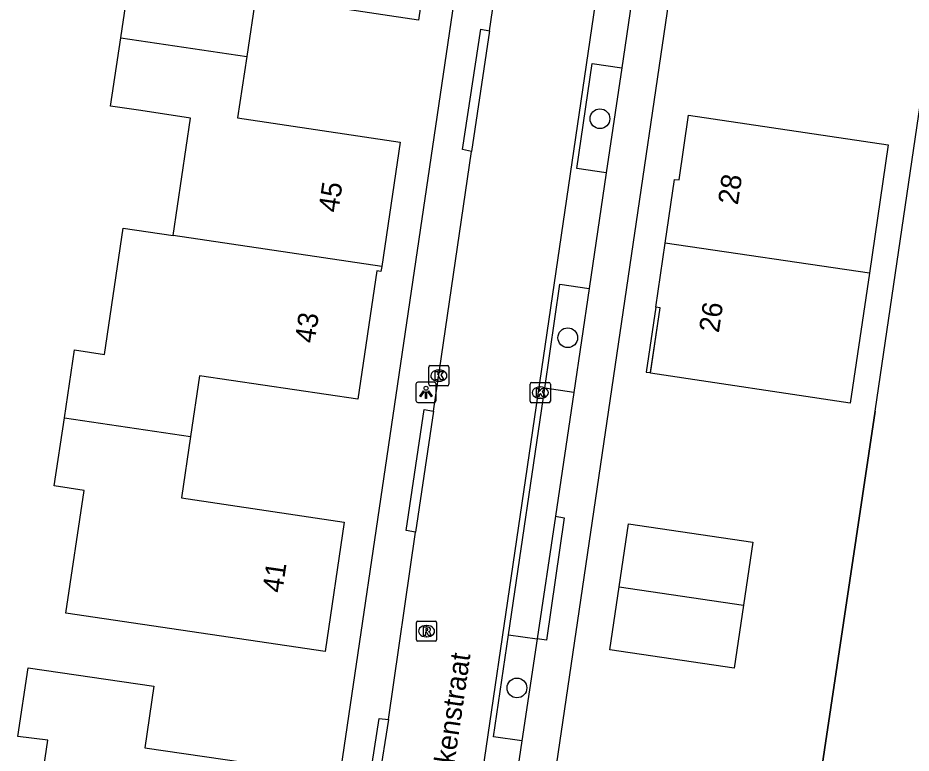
# Model space of a CAD drawing. Extents: x 164150 to 165261, y 382513 to 383432.
# Drawn here: x 164443.48 to 164487.69, y 383126.15 to 383162.53 of the extents above; entities that cross this region are included whole.
import ezdxf

# ---------------------------------------------------------------- set-up
doc = ezdxf.new("R2010")
doc.units = 0
for name, color, linetype in [('IMGEO_Boom', 7, 'Continuous'), ('IMGEO_Groenvoorziening', 7, 'Continuous'), ('IMGEO_Hek', 7, 'Continuous'), ('IMGEO_Kolk', 7, 'Continuous'), ('IMGEO_Lichtpunt', 7, 'Continuous'), ('IMGEO_Openbare_ruimte_label', 7, 'Continuous'), ('IMGEO_Pand', 7, 'Continuous'), ('IMGEO_Pand_nummerreeks', 7, 'Continuous'), ('IMGEO_Pand_overbouw', 7, 'Continuous'), ('IMGEO_Parkeervlak_open', 7, 'Continuous'), ('IMGEO_Rijbaan_lokaal_open', 7, 'Continuous'), ('IMGEO_Rioolput', 7, 'Continuous'), ('IMGEO_Voetpad_open', 7, 'Continuous')]:
    doc.layers.add(name, color=color, linetype=linetype)

msp = doc.modelspace()

# ---------------------------------------------------------------- linework, layer by layer
at = {"layer": 'IMGEO_Boom'}
for centre in [(164472.292, 383157.539), (164470.699, 383146.704), (164468.185, 383129.378)]:
    msp.add_circle(centre, 0.489, dxfattribs=at)
at = {"layer": 'IMGEO_Groenvoorziening'}
msp.add_lwpolyline([(164471.706, 383047.448), (164472.669, 383053.926), (164475.824, 383075.164), (164477.779, 383088.109), (164480.994, 383109.14), (164482.781, 383122.124), (164485.913, 383143.071), (164487.83, 383156.078), (164491.989, 383184.295), (164492.391, 383187.03)], dxfattribs=at)
at = {"layer": 'IMGEO_Hek'}
msp.add_lwpolyline([(164485.913, 383143.071), (164482.781, 383122.124)], dxfattribs=at)
at = {"layer": 'IMGEO_Kolk'}
for p, q in [((164463.817, 383144.4), (164463.817, 383145.252)), ((164463.892, 383145.326), (164464.744, 383145.326)), ((164464.818, 383145.252), (164464.818, 383144.4)), ((164464.305, 383145.106), (164464.33, 383145.106)), ((164464.328, 383144.546), (164464.303, 383144.546)), ((164468.836, 383143.562), (164468.836, 383144.414)), ((164468.911, 383144.488), (164469.763, 383144.488)), ((164469.837, 383144.414), (164469.837, 383143.562)), ((164464.744, 383144.326), (164463.892, 383144.326)), ((164469.324, 383144.268), (164469.349, 383144.268)), ((164469.763, 383143.488), (164468.911, 383143.488)), ((164469.347, 383143.708), (164469.322, 383143.708))]:
    msp.add_line(p, q, dxfattribs=at)
for points in [[(164463.817, 383144.4), (164463.817, 383145.252)], [(164463.892, 383145.326), (164464.744, 383145.326)], [(164464.818, 383145.252), (164464.818, 383144.4)], [(164464.138, 383145.026), (164464.261, 383145.026), (164464.261, 383144.875), (164464.391, 383145.026), (164464.555, 383145.026), (164464.409, 383144.875), (164464.562, 383144.626), (164464.41, 383144.626), (164464.325, 383144.79), (164464.261, 383144.723), (164464.261, 383144.626), (164464.138, 383144.626), (164464.138, 383145.026)], [(164468.836, 383143.562), (164468.836, 383144.414)], [(164468.911, 383144.488), (164469.763, 383144.488)], [(164469.837, 383144.414), (164469.837, 383143.562)], [(164464.744, 383144.326), (164463.892, 383144.326)], [(164469.157, 383144.188), (164469.28, 383144.188), (164469.28, 383144.037), (164469.41, 383144.188), (164469.574, 383144.188), (164469.428, 383144.037), (164469.581, 383143.788), (164469.429, 383143.788), (164469.344, 383143.952), (164469.28, 383143.885), (164469.28, 383143.788), (164469.157, 383143.788), (164469.157, 383144.188)], [(164469.763, 383143.488), (164468.911, 383143.488)]]:
    msp.add_lwpolyline(points, dxfattribs=at)
for centre, start, end in [((164463.894, 383145.25), 91.552, 178.448), ((164463.894, 383145.25), 91.552, 178.448), ((164464.742, 383145.25), 1.552, 88.448), ((164464.742, 383145.25), 1.552, 88.448), ((164463.894, 383144.402), 181.552, 268.448), ((164463.894, 383144.402), 181.552, 268.448), ((164464.742, 383144.402), 271.552, 358.448), ((164464.742, 383144.402), 271.552, 358.448), ((164468.913, 383144.412), 91.552, 178.448), ((164468.913, 383144.412), 91.552, 178.448), ((164469.761, 383144.412), 1.552, 88.448), ((164469.761, 383144.412), 1.552, 88.448), ((164468.913, 383143.564), 181.552, 268.448), ((164468.913, 383143.564), 181.552, 268.448), ((164469.761, 383143.564), 271.552, 358.448), ((164469.761, 383143.564), 271.552, 358.448)]:
    msp.add_arc(centre, 0.0765, start, end, dxfattribs=at)
for centre, major_axis, ratio, start_param, end_param in [((164464.304, 383144.826), (-0.387, 0.002), 0.722429, 4.712389, 7.853982), ((164464.329, 383144.826), (-0.39, 0.002), 0.717154, 1.570796, 4.712389), ((164469.323, 383143.988), (-0.387, 0.002), 0.722429, 4.712389, 7.853982), ((164469.348, 383143.988), (-0.39, 0.002), 0.717154, 1.570796, 4.712389)]:
    msp.add_ellipse(centre, major_axis=major_axis, ratio=ratio, start_param=start_param, end_param=end_param, dxfattribs=at)
at = {"layer": 'IMGEO_Lichtpunt'}
for p, q in [((164463.184, 383144.408), (164463.184, 383143.601)), ((164463.184, 383144.408), (164463.184, 383143.601)), ((164464.086, 383144.503), (164463.278, 383144.503)), ((164464.086, 383144.503), (164463.278, 383144.503)), ((164464.18, 383143.601), (164464.18, 383144.408)), ((164464.18, 383143.601), (164464.18, 383144.408)), ((164463.278, 383143.507), (164464.086, 383143.507)), ((164463.278, 383143.507), (164464.086, 383143.507))]:
    msp.add_line(p, q, dxfattribs=at)
for points in [[(164463.558, 383144.072), (164463.597, 383144.044), (164463.409, 383143.782), (164463.371, 383143.809), (164463.558, 383144.072)], [(164463.66, 383144.024), (164463.707, 383144.024), (164463.707, 383143.702), (164463.66, 383143.702), (164463.66, 383144.024)], [(164463.77, 383144.044), (164463.808, 383144.071), (164463.995, 383143.809), (164463.956, 383143.781), (164463.77, 383144.044)]]:
    msp.add_lwpolyline(points, dxfattribs=at)
msp.add_circle((164463.683, 383144.206), 0.0994, dxfattribs=at)
for centre, start, end in [((164463.278, 383144.408), 90, 180), ((164463.278, 383144.408), 90, 180), ((164464.086, 383144.408), 0, 90), ((164464.086, 383144.408), 0, 90), ((164463.278, 383143.601), 180, 270), ((164463.278, 383143.601), 180, 270), ((164464.086, 383143.601), 270, 0), ((164464.086, 383143.601), 270, 360)]:
    msp.add_arc(centre, 0.0946, start, end, dxfattribs=at)
at = {"layer": 'IMGEO_Pand'}
for points in [[(164448.577, 383161.535), (164449.079, 383164.893), (164453.035, 383164.322), (164453.867, 383169.902), (164451.375, 383170.273), (164451.41, 383170.512)], [(164464.221, 383168.616), (164463.319, 383162.42), (164455.265, 383163.627), (164454.814, 383160.612)], [(164451.171, 383151.755), (164452.032, 383157.572), (164449.568, 383157.941), (164448.073, 383158.164), (164448.577, 383161.535)], [(164448.577, 383161.535), (164454.814, 383160.612)], [(164454.814, 383160.612), (164454.361, 383157.584), (164462.411, 383156.38), (164461.491, 383150.228)], [(164475.522, 383151.386), (164475.989, 383154.535), (164476.215, 383154.513), (164476.68, 383157.719), (164486.56, 383156.24), (164485.631, 383149.89)], [(164445.788, 383142.741), (164446.292, 383146.105), (164447.773, 383145.88), (164448.702, 383152.121), (164451.171, 383151.755)], [(164461.491, 383150.228), (164451.171, 383151.755)], [(164485.631, 383149.89), (164484.677, 383143.468), (164474.788, 383144.95), (164475.267, 383148.176), (164475.051, 383148.212), (164475.522, 383151.386)], [(164485.631, 383149.89), (164475.522, 383151.386)], [(164461.491, 383150.228), (164461.453, 383149.98), (164461.255, 383150.011), (164460.307, 383143.671), (164452.474, 383144.81), (164452.034, 383141.817)], [(164452.034, 383141.817), (164451.589, 383138.786), (164459.633, 383137.587), (164458.691, 383131.184), (164445.853, 383133.073), (164446.764, 383139.152), (164445.283, 383139.378), (164445.788, 383142.741)], [(164445.788, 383142.741), (164452.034, 383141.817)], [(164473.246, 383134.382), (164473.705, 383137.499), (164479.851, 383136.594), (164479.392, 383133.476)], [(164479.392, 383133.476), (164478.933, 383130.359), (164472.787, 383131.264), (164473.246, 383134.382)], [(164473.246, 383134.382), (164479.392, 383133.476)], [(164444.041, 383120.553), (164444.974, 383126.801), (164443.483, 383126.973), (164443.999, 383130.378), (164450.216, 383129.466), (164449.77, 383126.419), (164457.596, 383125.271), (164456.658, 383118.873), (164456.869, 383118.864), (164456.839, 383118.659)]]:
    msp.add_lwpolyline(points, dxfattribs=at)
at = {"layer": 'IMGEO_Pand_overbouw'}
msp.add_lwpolyline([(164475.051, 383148.212), (164474.577, 383145.007), (164474.792, 383144.975), (164475.267, 383148.176)], close=True, dxfattribs=at)
at = {"layer": 'IMGEO_Parkeervlak_open'}
for points in [[(164472.603, 383154.855), (164471.151, 383155.072), (164471.914, 383160.266), (164473.369, 383160.049)], [(164469.557, 383144.209), (164470.312, 383149.353), (164471.76, 383149.141)], [(164467.766, 383132.011), (164469.557, 383144.209)], [(164471.001, 383143.997), (164469.557, 383144.209)], [(164468.43, 383126.759), (164467.025, 383126.965), (164467.766, 383132.011)], [(164467.766, 383132.011), (164469.182, 383131.803)]]:
    msp.add_lwpolyline(points, dxfattribs=at)
at = {"layer": 'IMGEO_Rijbaan_lokaal_open'}
for points in [[(164474.705, 383181.346), (164459.743, 383079.423)], [(164466.829, 383161.888), (164468.729, 383174.758)], [(164466.829, 383161.888), (164465.928, 383155.914)], [(164464.06, 383143.063), (164465.928, 383155.914)], [(164464.06, 383143.063), (164463.157, 383137.09)], [(164461.828, 383127.818), (164463.157, 383137.09)], [(164461.828, 383127.818), (164461.355, 383124.821)]]:
    msp.add_lwpolyline(points, dxfattribs=at)
at = {"layer": 'IMGEO_Rioolput'}
for p, q in [((164463.207, 383131.761), (164463.207, 383132.613)), ((164463.282, 383132.687), (164464.134, 383132.687)), ((164463.695, 383132.467), (164463.72, 383132.467)), ((164464.208, 383132.613), (164464.208, 383131.761)), ((164464.134, 383131.687), (164463.282, 383131.687)), ((164463.718, 383131.907), (164463.693, 383131.907))]:
    msp.add_line(p, q, dxfattribs=at)
for points in [[(164463.207, 383131.761), (164463.207, 383132.613)], [(164463.282, 383132.687), (164464.134, 383132.687)], [(164464.208, 383132.613), (164464.208, 383131.761)], [(164463.796, 383132.385), (164463.544, 383132.387), (164463.544, 383131.987)], [(164463.544, 383131.987), (164463.668, 383131.987), (164463.668, 383132.149), (164463.679, 383132.149)], [(164463.722, 383132.306), (164463.668, 383132.306), (164463.668, 383132.225)], [(164463.668, 383132.225), (164463.72, 383132.225)], [(164463.726, 383132.12), (164463.797, 383131.987), (164463.937, 383131.987), (164463.872, 383132.113)], [(164464.134, 383131.687), (164463.282, 383131.687)]]:
    msp.add_lwpolyline(points, dxfattribs=at)
for centre, radius, start, end in [((164463.284, 383132.611), 0.0765, 91.552, 178.448), ((164463.284, 383132.611), 0.0765, 91.552, 178.448), ((164464.132, 383132.611), 0.0765, 1.552, 88.448), ((164464.132, 383132.611), 0.0765, 1.552, 88.448), ((164463.678, 383132.096), 0.0533, 26.0293, 88.6989), ((164463.704, 383132.414), 0.19, 274.7715, 282.9687), ((164463.728, 383132.21), 0.0964, 77.0061, 93.1865), ((164463.742, 383132.267), 0.0378, 276.6634, 79.6772), ((164463.795, 383132.275), 0.109, 350.3612, 89.416), ((164463.793, 383132.275), 0.112, 277.5842, 350.9817), ((164463.777, 383132.06), 0.108, 29.5134, 73.7905), ((164463.284, 383131.763), 0.0765, 181.552, 268.448), ((164463.284, 383131.763), 0.0765, 181.552, 268.448), ((164464.132, 383131.763), 0.0765, 271.552, 358.448), ((164464.132, 383131.763), 0.0765, 271.552, 358.448)]:
    msp.add_arc(centre, radius, start, end, dxfattribs=at)
for centre, major_axis, ratio, start_param, end_param in [((164463.694, 383132.187), (-0.387, 0.002), 0.722429, 4.712389, 7.853982), ((164463.719, 383132.187), (-0.39, 0.002), 0.717154, 1.570796, 4.712389)]:
    msp.add_ellipse(centre, major_axis=major_axis, ratio=ratio, start_param=start_param, end_param=end_param, dxfattribs=at)
at = {"layer": 'IMGEO_Voetpad_open'}
for points in [[(164468.608, 383187.386), (164452.978, 383081.464)], [(164479.002, 383185.851), (164461.739, 383068.623)], [(164474.249, 383166.01), (164473.369, 383160.049)], [(164465.928, 383155.914), (164465.483, 383156.011), (164466.399, 383161.964), (164466.829, 383161.888)], [(164473.369, 383160.049), (164472.603, 383154.855)], [(164472.603, 383154.855), (164471.76, 383149.141)], [(164471.76, 383149.141), (164471.001, 383143.997)], [(164471.001, 383143.997), (164470.098, 383137.877)], [(164463.157, 383137.09), (164462.704, 383137.16), (164463.598, 383143.151), (164464.06, 383143.063)], [(164470.098, 383137.877), (164470.524, 383137.797), (164469.647, 383131.746), (164469.182, 383131.803)], [(164470.098, 383137.877), (164469.182, 383131.803)], [(164469.182, 383131.803), (164468.43, 383126.759)], [(164461.355, 383124.821), (164460.906, 383124.891), (164461.372, 383127.859), (164461.828, 383127.818)], [(164468.43, 383126.759), (164466.752, 383115.492)]]:
    msp.add_lwpolyline(points, dxfattribs=at)

# ---------------------------------------------------------------- texts
at = {"layer": 'IMGEO_Openbare_ruimte_label'}
msp.add_text('Paukenstraat', height=1, rotation=81.6591, dxfattribs=at).set_placement((164464.743, 383123.234))
at = {"layer": 'IMGEO_Pand_nummerreeks'}
for s, rotation, p in [('28', 81.5578, (164479.113, 383153.241)), ('45', 81.4906, (164459.337, 383152.862)), ('26', 81.5578, (164478.174, 383146.916)), ('43', 81.4923, (164458.167, 383146.399)), ('41', 81.6296, (164456.565, 383134.047))]:
    msp.add_text(s, height=1, rotation=rotation, dxfattribs=at).set_placement(p)

doc.saveas('drawing.dxf')
